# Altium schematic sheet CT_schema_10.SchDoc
size 274 x 160 mm
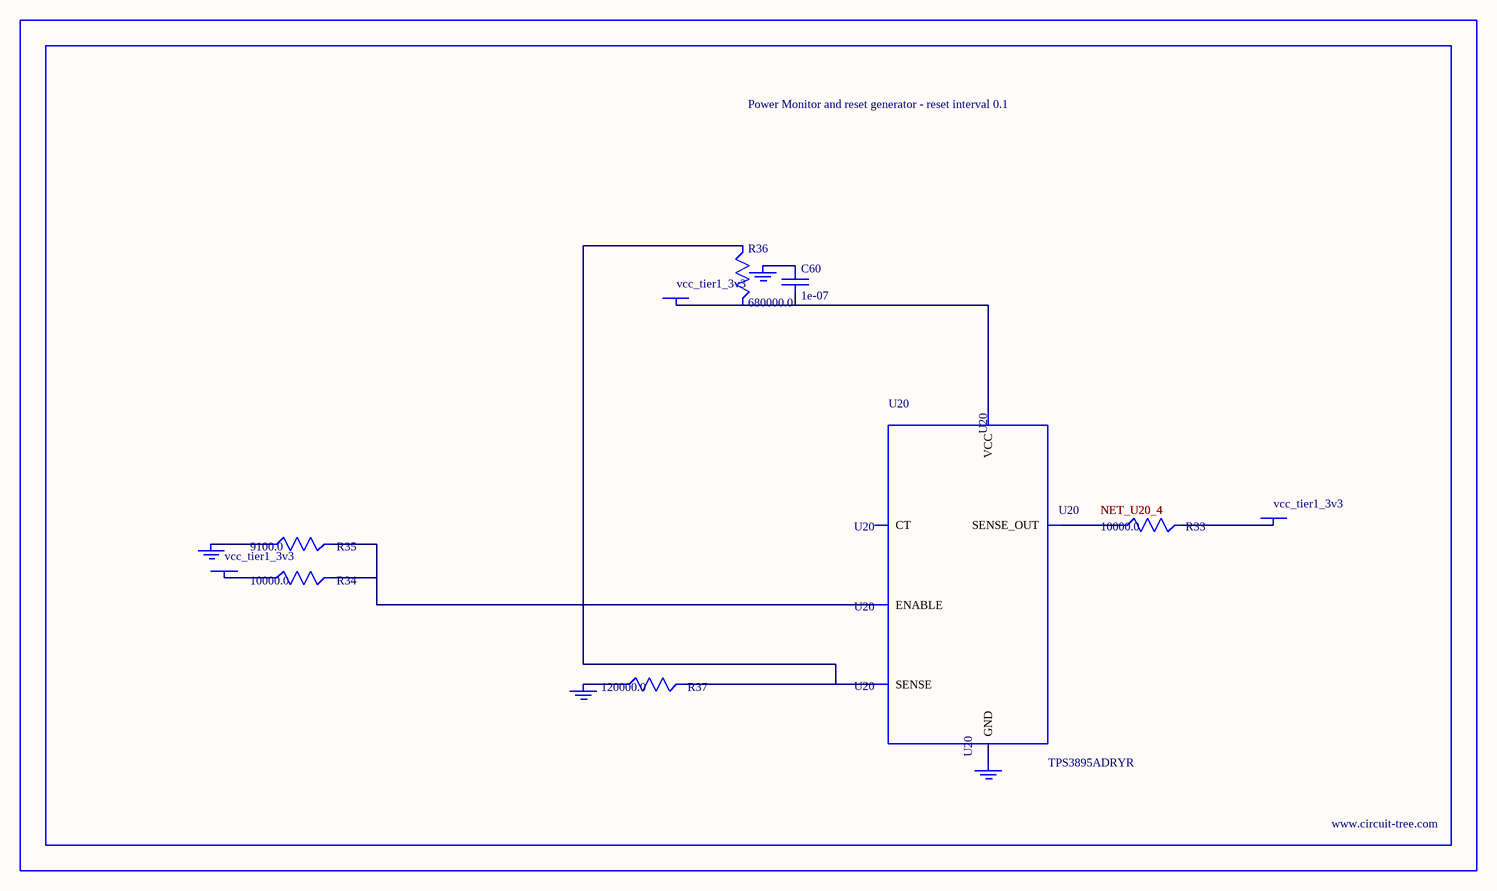
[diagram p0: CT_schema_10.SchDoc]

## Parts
BORDER9  (no value)
C60  1e-07  [C0402]
GND_INSTANCE_9_0  (no value)
GND_INSTANCE_9_1  (no value)
GND_INSTANCE_9_2  (no value)
GND_INSTANCE_9_3  (no value)
POWER_INSTANCE_9_0  vcc_tier1_3v3
POWER_INSTANCE_9_1  vcc_tier1_3v3
POWER_INSTANCE_9_2  vcc_tier1_3v3
R33  10000.0  [R0603]
R34  10000.0  [R0603]
R35  9100.0  [R0603]
R36  680000.0  [R0603]
R37  120000.0  [R0603]
U20  TPS3895ADRYR  [SON-6]

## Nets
NetC60_1: C60.1 GND_INSTANCE_9_2.0(GND)
NetC60_2: C60.2 POWER_INSTANCE_9_2.0(PWR) R36.2 U20.6(VCC)
NetGND_INSTANCE_9_0_0: GND_INSTANCE_9_0.0(GND) R35.1
NetGND_INSTANCE_9_1_0: GND_INSTANCE_9_1.0(GND) R37.1
NetGND_INSTANCE_9_3_0: GND_INSTANCE_9_3.0(GND) U20.2(GND)
NetPOWER_INSTANCE_9_0_0: POWER_INSTANCE_9_0.0(PWR) R34.1
NetPOWER_INSTANCE_9_1_0: POWER_INSTANCE_9_1.0(PWR) R33.2
NetR33_1: R33.1 U20.4(SENSE_OUT)
NetR34_2: R34.2 R35.2 U20.1(ENABLE)
NetR36_1: R36.1 R37.2 U20.3(SENSE)

Not connected (* = marked no-connect by the designer): U20 5(CT)

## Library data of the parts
BORDER9 = BORDER_PAGE9
C60 = C0402C104K3RACTU
GND_INSTANCE_9_0-GND_INSTANCE_9_3 = GND
POWER_INSTANCE_9_0-POWER_INSTANCE_9_2 = PWR
R33 R34 = RC0603JR-0710KL
R35 = RC0603JR-079K1L
R36 = RC0603JR-07680KL
R37 = RC0603JR-07120KL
